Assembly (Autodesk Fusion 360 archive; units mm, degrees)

design "Assembly" references "TOP", "MIRROR-1", "innestiTop", "3DP-mirrors-holder-x1", "baseUV_Front", "3DP-mirrors-holder-x2", "MIRROR-2", "baseUV_Rear", "3DP-mirrors-laser-body", "baseUV_Lateral"
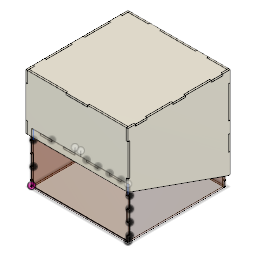
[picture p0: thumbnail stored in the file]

design "TOP" references "Tleft", "Tright", "ps", "Trear", "Tfront", "Ttop"
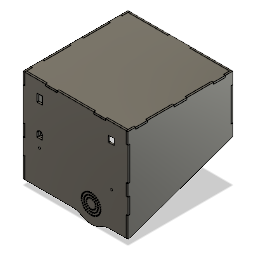
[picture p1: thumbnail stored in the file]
component_insert "Component Insert1"
component_insert "Component Insert2"
component_insert "Component Insert3"
component_insert "Component Insert4"
component_insert "Component Insert5"
component_insert "Component Insert6"
joint "Assemble1" OffsetX 0 OffsetY 0 OffsetZ 0 AngleZ 0 OffsetX 0 OffsetY 0 OffsetZ 0 AngleZ 0 alignAngle 0 alignOffsetX 0 alignOffsetY 0 alignOffsetZ 0
joint "Assemble2" OffsetX 0 OffsetY 0 OffsetZ 0 AngleZ 0 OffsetX 0 OffsetY 0 OffsetZ 0 AngleZ 0 alignAngle 0 alignOffsetX 0 alignOffsetY 0 alignOffsetZ 0
joint "Assemble3" OffsetX 0 OffsetY 0 OffsetZ 0 AngleZ 0 OffsetX 0 OffsetY 0 OffsetZ 0 AngleZ 0 alignAngle -90 alignOffsetX 0 alignOffsetY 0 alignOffsetZ 0
joint "Assemble4" OffsetX 0 OffsetY 0 OffsetZ 0 AngleZ 0 OffsetX 0 OffsetY 0 OffsetZ 0 AngleZ 0 alignAngle -90 alignOffsetX 0 alignOffsetY 0 alignOffsetZ 0
position "Position1"
joint "Assemble5" OffsetX 0 OffsetY 0 OffsetZ 0 AngleZ 0 OffsetX 0 OffsetY 0 OffsetZ 0 AngleZ 0 alignAngle 180 alignOffsetX 0 alignOffsetY 0 alignOffsetZ 0

design "innestiTop"
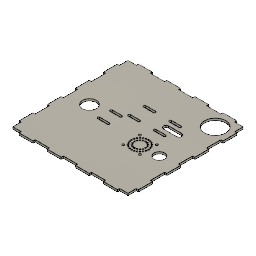
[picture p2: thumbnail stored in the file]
sketch "Sketch1" plane through (0, 0, 0) normal (0, 1, 0) x axis (1, 0, 0)
  line L1 (12, -3) -> (32, -3)
  line L2 (0, 52) -> (0, 32)
  line L3 (92, 0) -> (92, -3)
  line L4 (164, 112) -> (164, 132)
  line L5 (152, 0) -> (164, 0)
  line L6 (92, -3) -> (112, -3)
  line L7 (112, 0) -> (132, 0)
  line L8 (0, 132) -> (0, 112)
  line L9 (0, 0) -> (12, 0)
  line L10 (12, 0) -> (12, -3)
  line L11 (132, 164) -> (112, 164)
  line L12 (167, 112) -> (164, 112)
  line L13 (167, 92) -> (167, 112)
  line L14 (-3, 32) -> (-3, 12)
  line L15 (12, 167) -> (12, 164)
  line L16 (32, 0) -> (52, 0)
  line L17 (-3, 72) -> (-3, 52)
  line L18 (132, -3) -> (152, -3)
  line L19 (52, -3) -> (72, -3)
  line L20 (112, -3) -> (112, 0)
  line L21 (0, 72) -> (-3, 72)
  line L22 (52, 0) -> (52, -3)
  line L23 (0, 92) -> (0, 72)
  line L24 (72, 0) -> (82, 0)
  line L25 (0, 32) -> (-3, 32)
  line L26 (0, 12) -> (0, 0)
  line L27 (-3, 92) -> (0, 92)
  line L28 (82, 0) -> (92, 0)
  line L29 (164, 92) -> (167, 92)
  line L30 (167, 132) -> (167, 152)
  line L31 (32, -3) -> (32, 0)
  line L32 (152, 164) -> (152, 167)
  line L33 (112, 167) -> (92, 167)
  line L34 (132, 167) -> (132, 164)
  line L35 (152, -3) -> (152, 0)
  line L36 (-3, 112) -> (-3, 92)
  line L37 (0, 152) -> (-3, 152)
  line L38 (-3, 52) -> (0, 52)
  line L39 (132, 0) -> (132, -3)
  line L40 (72, 167) -> (52, 167)
  line L41 (164, 132) -> (167, 132)
  line L42 (164, 0) -> (164, 12)
  line L43 (92, 164) -> (82, 164)
  line L44 (72, 164) -> (72, 167)
  line L45 (32, 164) -> (32, 167)
  line L46 (72, -3) -> (72, 0)
  line L47 (-3, 12) -> (0, 12)
  line L48 (167, 52) -> (167, 72)
  line L49 (-3, 132) -> (0, 132)
  line L50 (164, 72) -> (164, 92)
  line L51 (50.0833, 88.2393) -> (64.0834, 88.2393)
  line L52 (164, 152) -> (164, 164)
  line L53 (52, 164) -> (32, 164)
  line L54 (0, 112) -> (-3, 112)
  line L55 (50.0833, 70.4393) -> (64.0834, 70.4393)
  line L56 (-3, 152) -> (-3, 132)
  line L57 (164, 164) -> (152, 164)
  line L58 (92, 167) -> (92, 164)
  line L59 (164, 32) -> (164, 52)
  line L60 (112, 164) -> (112, 167)
  line L61 (119.122, 120.6372) -> (105.122, 120.6372)
  line L62 (152, 167) -> (132, 167)
  line L63 (109.722, 104.7454) -> (128.522, 104.7454)
  line L64 (164, 52) -> (167, 52)
  line L65 (167, 152) -> (164, 152)
  line L66 (0, 164) -> (0, 152)
  line L67 (82, 164) -> (72, 164)
  line L68 (68.5922, 117.4372) -> (82.5922, 117.4372)
  line L69 (82.5922, 98.6372) -> (68.5922, 98.6372)
  line L70 (164, 12) -> (167, 12)
  line L71 (12, 164) -> (0, 164)
  line L72 (167, 12) -> (167, 32)
  line L73 (64.0834, 73.6393) -> (50.0833, 73.6393)
  line L74 (64.0834, 91.4393) -> (50.0833, 91.4393)
  line L75 (68.5922, 95.4372) -> (82.5922, 95.4372)
  line L76 (52, 167) -> (52, 164)
  line L77 (32, 167) -> (12, 167)
  line L78 (105.122, 95.4372) -> (119.122, 95.4372)
  line L79 (82.5922, 120.6372) -> (68.5922, 120.6372)
  line L80 (167, 72) -> (164, 72)
  line L81 (105.122, 117.4372) -> (119.122, 117.4372)
  line L82 (167, 32) -> (164, 32)
  line L83 (128.522, 111.9454) -> (109.722, 111.9454)
  line L84 (119.122, 98.6372) -> (105.122, 98.6372)
  arc A1 centre (119.122, 97.0372) radius 1.6 clockwise from (119.122, 98.6372) to (119.122, 95.4372)
  circle C1 centre (102.282, 62.3858) radius 1
  circle C2 centre (123.0667, 74.3858) radius 1
  circle C3 centre (106.6743, 57.9935) radius 1
  circle C4 centre (104.1891, 59.9005) radius 1
  arc A2 centre (119.122, 119.0372) radius 1.6 clockwise from (119.122, 120.6372) to (119.122, 117.4372)
  arc A3 centre (105.122, 97.0372) radius 1.6 clockwise from (105.122, 95.4372) to (105.122, 98.6372)
  arc A4 centre (82.5922, 97.0372) radius 1.6 clockwise from (82.5922, 98.6372) to (82.5922, 95.4372)
  arc A5 centre (68.5922, 119.0372) radius 1.6 clockwise from (68.5922, 117.4372) to (68.5922, 120.6372)
  circle C5 centre (121.1596, 59.9005) radius 1
  circle C6 centre (100.6743, 68.3858) radius 1
  circle C7 centre (115.7802, 56.7947) radius 1
  circle C8 centre (124.2655, 65.2799) radius 1
  circle C9 centre (118.3312, 74.0426) radius 1
  circle C10 centre (143.9805, 144.0319) radius 15
  circle C11 centre (115.7802, 79.9769) radius 1
  arc A6 centre (109.722, 108.3454) radius 3.6 clockwise from (109.722, 104.7454) to (107.1764, 110.891)
  circle C12 centre (112.6743, 56.3858) radius 1
  circle C13 centre (102.282, 74.3858) radius 1
  circle C14 centre (124.2655, 71.4916) radius 1
  arc A7 centre (82.5922, 119.0372) radius 1.6 clockwise from (82.5922, 120.6372) to (82.5922, 117.4372)
  arc A8 centre (50.0833, 72.0393) radius 1.6 clockwise from (50.0833, 70.4393) to (50.0833, 73.6393)
  arc A9 centre (64.0833, 72.0393) radius 1.6 clockwise from (64.0834, 73.6393) to (64.0834, 70.4393)
  arc A10 centre (105.122, 119.0372) radius 1.6 clockwise from (105.122, 117.4372) to (105.122, 120.6372)
  arc A11 centre (109.593, 108.6567) radius 3.2912 clockwise from (107.1764, 110.891) to (109.722, 111.9454)
  arc A12 centre (128.522, 108.3454) radius 3.6 clockwise from (128.522, 111.9454) to (128.522, 104.7454)
  circle C15 centre (109.5685, 79.9769) radius 1
  circle C16 centre (101.0832, 65.2799) radius 1
  circle C17 centre (107.0175, 62.7289) radius 1
  circle C18 centre (120.6743, 68.3858) radius 1
  circle C19 centre (140.2292, 68.3858) radius 7.5
  circle C20 centre (115.7358, 75.7768) radius 1
  circle C21 centre (106.6743, 78.7781) radius 1
  circle C22 centre (101.0832, 71.4916) radius 1
  circle C23 centre (118.6743, 57.9935) radius 1
  arc A13 centre (68.5922, 97.0372) radius 1.6 clockwise from (68.5922, 95.4372) to (68.5922, 98.6372)
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extrude "Extrude1" new body sketch "Sketch1" along normal blind 3

design "baseUV_Rear"
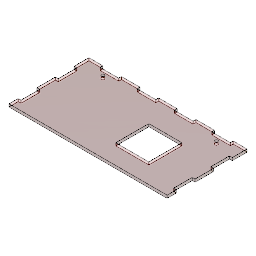
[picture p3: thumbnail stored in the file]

design "baseUV_Front"
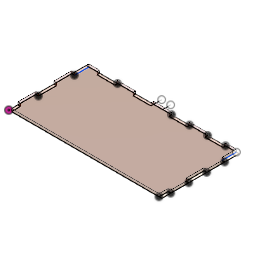
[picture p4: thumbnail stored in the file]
sketch "Sketch1" plane through (0, 0, 0) normal (0, 1, 0) x axis (1, 0, 0)
  line L1 (170, 0) -> (0, 0)
  line L2 (170, 86) -> (170, 0)
  line L3 (0, 86) -> (170, 86)
  line L4 (0, 0) -> (0, 86)
  line L5 (3, 0) -> (0, 0)
  line L6 (3, 10) -> (3, 0)
  line L7 (0, 10) -> (3, 10)
  line L8 (0, 0) -> (0, 10)
  line L9 (0, 30) -> (3, 30)
  line L10 (3, 30) -> (0, 30)
  line L11 (3, 50) -> (3, 30)
  line L12 (0, 50) -> (3, 50)
  line L13 (0, 30) -> (0, 50)
  line L14 (0, 70) -> (3, 70)
  line L15 (3, 70) -> (0, 70)
  line L16 (3, 86) -> (3, 70)
  line L17 (0, 86) -> (3, 86)
  line L18 (0, 70) -> (0, 86)
  line L19 (85, 95) -> (85, 86)
  line L20 (167, 86) -> (167, 70)
  line L21 (167, 70) -> (170, 70)
  line L22 (170, 50) -> (167, 50)
  line L23 (167, 30) -> (170, 30)
  line L24 (170, 10) -> (167, 10)
  line L25 (167, 10) -> (167, 0)
  line L26 (167, 50) -> (167, 30)
  line L27 (75, 95) -> (75, 86)
  line L28 (55, 86) -> (75, 86)
  line L29 (55, 83) -> (55, 86)
  line L30 (75, 83) -> (55, 83)
  line L31 (75, 86) -> (75, 83)
  line L32 (35, 83) -> (35, 86)
  line L33 (15, 83) -> (35, 83)
  line L34 (15, 86) -> (15, 83)
  line L35 (35, 86) -> (15, 86)
  line L36 (35, 83) -> (35, 86)
  line L37 (155, 86) -> (155, 83)
  line L38 (155, 83) -> (135, 83)
  line L39 (135, 83) -> (135, 86)
  line L40 (115, 83) -> (115, 86)
  line L41 (95, 83) -> (115, 83)
  line L42 (95, 86) -> (95, 83)
  point P2 (0, 0)
  point P3 (170, 0)
  point P5 (0, 86)
  point P6 (0, 0)
  point P9 (0, 10)
  point P7 (3, 0)
  point P11 (0, 30)
  point P14 (0, 50)
  point P12 (3, 30)
  point P32 (75, 86)
  point P34 (55, 86)
  point P36 (75, 83)
  point P38 (35, 83)
  point P39 (15, 83)
  point P41 (35, 86)
  dimension "d1" distance P2 P3 = 170
  dimension "d2" distance P2 P5 = 86
  dimension "d3" distance P6 P9 = 10
  dimension "d4" distance P6 P7 = 3
  dimension "d5" = 20
  dimension "d6" distance P11 P14 = 20
  dimension "d7" distance P11 P12 = 3
  dimension "d8" = 20
  dimension "d11" = 10
  dimension "d12" distance P32 P34 = 20
  dimension "d13" distance P32 P36 = 3
  dimension "d14" = 20
  dimension "d15" distance P38 P39 = 20
  dimension "d16" distance P38 P41 = 3
extrude "Extrude2" new body sketch "Sketch1" profile of L1 L2 L3 L4 L6 L7 L9 L10 L11 L12 L14 L15 L16 L20 L21 L22 L23 L24 L25 L26 L29 L30 L31 L32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 along normal blind 3
component_from_bodies "Body->Comp"
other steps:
base_feature "Base Feature"
create_component "CreateComponent1"
remove_body "RemoveBody1"

design "3DP-mirrors-holder-x1"
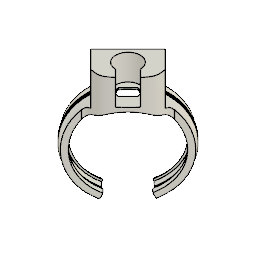
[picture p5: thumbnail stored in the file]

design "Trear"
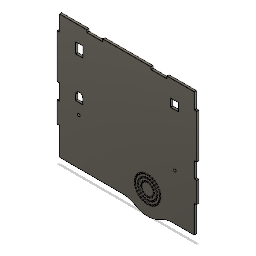
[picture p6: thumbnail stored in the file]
sketch "topRear" plane through (0, 0, 0) normal (0, 0, 1) x axis (1, 0, 0)
  line L1 (-742.1707, 154.2015) -> (-715.123, 154.2015)
  line L2 (-830.923, 309.2015) -> (-850.923, 309.2015)
  line L3 (-888.923, 292.2015) -> (-888.923, 236.2015)
  line L4 (-888.923, 189.2015) -> (-885.923, 189.2015)
  line L5 (-856.173, 278.6015) -> (-856.173, 291.6015)
  line L6 (-744.523, 280.1515) -> (-734.623, 280.1515)
  line L7 (-865.123, 227.2015) -> (-856.223, 227.2015)
  line L8 (-711.323, 292.2015) -> (-714.323, 292.2015)
  line L9 (-885.923, 189.2015) -> (-885.923, 174.2015)
  line L10 (-769.323, 309.2015) -> (-769.323, 312.2015)
  line L11 (-830.923, 312.2015) -> (-830.923, 309.2015)
  line L12 (-711.323, 236.2015) -> (-711.323, 292.2015)
  line L13 (-888.923, 236.2015) -> (-885.923, 236.2015)
  line L14 (-850.923, 312.2015) -> (-885.923, 312.2015)
  line L15 (-714.323, 292.2015) -> (-714.323, 312.2015)
  line L16 (-885.923, 312.2015) -> (-885.923, 292.2015)
  line L17 (-714.323, 154.2015) -> (-714.323, 174.2015)
  line L18 (-744.523, 290.0515) -> (-744.523, 280.1515)
  line L19 (-769.323, 312.2015) -> (-830.923, 312.2015)
  line L20 (-856.223, 227.2015) -> (-856.223, 234.1515)
  line L21 (-885.923, 236.2015) -> (-885.923, 216.2015)
  line L22 (-856.173, 291.6015) -> (-865.173, 291.6015)
  line L23 (-714.323, 174.2015) -> (-714.323, 189.2015)
  line L24 (-865.173, 278.6015) -> (-856.173, 278.6015)
  line L25 (-715.123, 154.2015) -> (-714.323, 154.2015)
  line L26 (-885.923, 292.2015) -> (-888.923, 292.2015)
  line L27 (-734.623, 280.1515) -> (-734.623, 290.0515)
  line L28 (-711.323, 216.2015) -> (-714.323, 216.2015)
  line L29 (-885.923, 154.2015) -> (-805.3845, 154.2015)
  line L30 (-850.923, 309.2015) -> (-850.923, 312.2015)
  line L31 (-714.323, 216.2015) -> (-714.323, 236.2015)
  line L32 (-865.173, 291.6015) -> (-865.173, 278.6015)
  line L33 (-749.323, 312.2015) -> (-749.323, 309.2015)
  line L34 (-749.323, 309.2015) -> (-769.323, 309.2015)
  line L35 (-714.323, 189.2015) -> (-711.323, 189.2015)
  line L36 (-714.323, 236.2015) -> (-711.323, 236.2015)
  line L37 (-885.923, 174.2015) -> (-885.923, 154.2015)
  line L38 (-865.123, 234.1515) -> (-865.123, 227.2015)
  line L39 (-714.323, 312.2015) -> (-749.323, 312.2015)
  line L40 (-885.923, 216.2015) -> (-888.923, 216.2015)
  line L41 (-888.923, 216.2015) -> (-888.923, 189.2015)
  line L42 (-711.323, 189.2015) -> (-711.323, 216.2015)
  line L43 (-734.623, 290.0515) -> (-744.523, 290.0515)
  circle C1 centre (-779.4345, 169.5446) radius 1
  circle C2 centre (-773.7776, 167.2015) radius 1
  circle C3 centre (-776.8391, 182.5925) radius 1
  circle C4 centre (-766.3866, 172.14) radius 1
  arc A1 centre (-742.1707, 124.2015) radius 30 clockwise from (-757.9742, 149.7015) to (-742.1707, 154.2015)
  circle C5 centre (-779.4345, 180.8583) radius 1
  circle C6 centre (-781.1687, 178.263) radius 1
  circle C7 centre (-773.7776, 187.2015) radius 1
  arc A2 centre (-860.673, 234.1515) radius 4.45 clockwise from (-865.123, 234.1515) to (-856.223, 234.1515)
  circle C8 centre (-781.7776, 175.2015) radius 1
  circle C9 centre (-781.1687, 172.14) radius 1
  circle C10 centre (-776.8391, 167.8105) radius 1
  circle C11 centre (-770.7161, 167.8105) radius 1
  circle C12 centre (-768.1208, 169.5446) radius 1
  circle C13 centre (-773.7776, 191.2015) radius 1
  circle C14 centre (-765.7776, 175.2015) radius 1
  circle C15 centre (-773.7776, 183.2015) radius 1
  circle C16 centre (-785.3687, 178.3073) radius 1
  circle C17 centre (-782.2629, 166.7162) radius 1
  circle C18 centre (-785.3687, 172.0957) radius 1
  circle C19 centre (-767.7776, 164.8092) radius 1
  arc A3 centre (-805.3845, 124.2015) radius 30 clockwise from (-805.3845, 154.2015) to (-789.5811, 149.7015)
  arc A4 centre (-773.7776, 175.2015) radius 30 clockwise from (-757.9742, 149.7015) to (-789.5811, 149.7015)
  circle C20 centre (-760.4741, 166.3124) radius 1
  circle C21 centre (-758.0851, 172.08) radius 1
  circle C22 centre (-782.6667, 188.505) radius 1
  circle C23 centre (-782.2629, 183.6868) radius 1
  circle C24 centre (-779.9006, 160.4194) radius 1
  circle C25 centre (-770.6562, 159.5089) radius 1
  circle C26 centre (-788.5597, 169.0786) radius 1
  circle C27 centre (-758.9955, 181.3244) radius 1
  circle C28 centre (-766.3866, 178.263) radius 1
  circle C29 centre (-770.7161, 182.5925) radius 1
  circle C30 centre (-787.0811, 184.0906) radius 1
  circle C31 centre (-762.4639, 186.5152) radius 1
  circle C32 centre (-757.7776, 175.2015) radius 1
  circle C33 centre (-776.8834, 163.6104) radius 1
  circle C34 centre (-785.0913, 163.8878) radius 1
  circle C35 centre (-779.7776, 164.8092) radius 1
  circle C36 centre (-785.7776, 175.2015) radius 1
  circle C37 centre (-776.8991, 190.8941) radius 1
  circle C38 centre (-758.0851, 178.3229) radius 1
  circle C39 centre (-785.0913, 186.5152) radius 1
  circle C40 centre (-762.1865, 178.3073) radius 1
  circle C41 centre (-788.5597, 181.3244) radius 1
  circle C42 centre (-767.6547, 189.9836) radius 1
  circle C43 centre (-763.3853, 181.2015) radius 1
  circle C44 centre (-758.9955, 169.0786) radius 1
  circle C45 centre (-760.4741, 184.0906) radius 1
  circle C46 centre (-768.1208, 180.8583) radius 1
  circle C47 centre (-773.7776, 163.2015) radius 1
  circle C48 centre (-767.7776, 185.5938) radius 1
  circle C49 centre (-784.1699, 181.2015) radius 1
  circle C50 centre (-762.4639, 163.8878) radius 1
  circle C51 centre (-770.6718, 186.7926) radius 1
  circle C52 centre (-765.2923, 183.6868) radius 1
  circle C53 centre (-763.3853, 169.2015) radius 1
  circle C54 centre (-787.0811, 166.3124) radius 1
  circle C55 centre (-767.6547, 160.4194) radius 1
  circle C56 centre (-789.7776, 175.2015) radius 1
  circle C57 centre (-776.8834, 186.7926) radius 1
  circle C58 centre (-761.7776, 175.2015) radius 1
  circle C59 centre (-770.6562, 190.8941) radius 1
  circle C60 centre (-764.8885, 188.505) radius 1
  circle C61 centre (-764.8885, 161.898) radius 1
  circle C62 centre (-773.7776, 159.2015) radius 1
  circle C63 centre (-789.4702, 172.08) radius 1
  circle C64 centre (-779.9006, 189.9836) radius 1
  circle C65 centre (-789.4702, 178.3229) radius 1
  circle C66 centre (-776.8991, 159.5089) radius 1
  circle C67 centre (-739.123, 213.2014) radius 1.6
  circle C68 centre (-784.1699, 169.2015) radius 1
  circle C69 centre (-861.123, 213.2014) radius 1.6
  circle C70 centre (-779.7776, 185.5938) radius 1
  circle C71 centre (-770.6718, 163.6104) radius 1
  circle C72 centre (-765.2923, 166.7162) radius 1
  circle C73 centre (-782.6667, 161.898) radius 1
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extrude "Extrude1" new body sketch "topRear" along normal blind 3

design "3DP-mirrors-holder-x2"
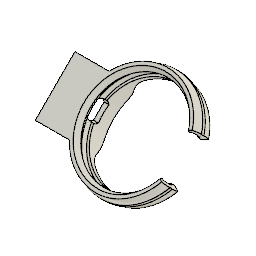
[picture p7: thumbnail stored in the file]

design "MIRROR-2"
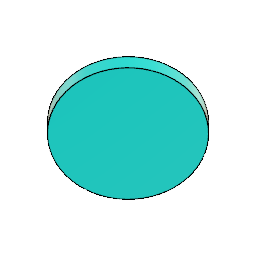
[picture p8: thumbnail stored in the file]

design "ps"
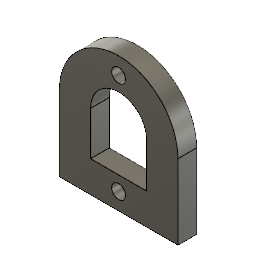
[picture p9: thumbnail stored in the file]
sketch "topPowerSupply" plane through (0, 0, 0) normal (0, 0, 1) x axis (1, 0, 0)
  line L1 (-593.1333, 438.9132) -> (-593.1333, 450.8632)
  line L2 (-607.0333, 450.8632) -> (-607.0333, 443.9132)
  line L3 (-612.0333, 438.9132) -> (-593.1333, 438.9132)
  line L4 (-598.1333, 443.9132) -> (-598.1333, 450.8632)
  line L5 (-607.0333, 443.9132) -> (-598.1333, 443.9132)
  line L6 (-612.0333, 450.8632) -> (-612.0333, 438.9132)
  circle C1 centre (-602.5833, 441.6132) radius 1.1
  arc A1 centre (-602.5833, 450.8632) radius 9.45 clockwise from (-612.0333, 450.8632) to (-593.1333, 450.8632)
  circle C2 centre (-602.5833, 457.6132) radius 1.1
  arc A2 centre (-602.5833, 450.8632) radius 4.45 clockwise from (-607.0333, 450.8632) to (-598.1333, 450.8632)
extrude "Extrude1" new body sketch "topPowerSupply" along normal blind 3

design "baseUV_Lateral"
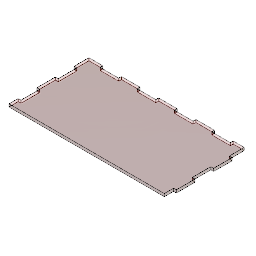
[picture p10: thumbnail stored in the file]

design "Tright"
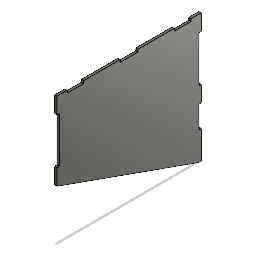
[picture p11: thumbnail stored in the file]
sketch "topRight" plane through (0, 0, 0) normal (1, 0, 0) x axis (0, 0, -1)
  line L1 (-505.2969, 687.289) -> (-505.2969, 707.289)
  line L2 (-472.2969, 707.289) -> (-427.2969, 707.289)
  line L3 (-502.2969, 687.289) -> (-505.2969, 687.289)
  line L4 (-330.6969, 631.289) -> (-327.6969, 631.289)
  line L5 (-492.2969, 704.289) -> (-472.2969, 704.289)
  line L6 (-505.2969, 707.289) -> (-502.2969, 707.289)
  line L7 (-427.2969, 704.289) -> (-405.6969, 704.289)
  line L8 (-405.6969, 707.289) -> (-360.6969, 707.289)
  line L9 (-427.2969, 707.289) -> (-427.2969, 704.289)
  line L10 (-502.2969, 707.289) -> (-492.2969, 707.289)
  line L11 (-340.6969, 707.289) -> (-330.6969, 707.289)
  line L12 (-330.6969, 611.289) -> (-330.6969, 584.289)
  line L13 (-327.6969, 569.289) -> (-327.6969, 549.289)
  line L14 (-360.6969, 704.289) -> (-340.6969, 704.289)
  line L15 (-330.6969, 707.289) -> (-327.6969, 707.289)
  line L16 (-327.6969, 611.289) -> (-330.6969, 611.289)
  line L17 (-330.6969, 584.289) -> (-327.6969, 584.289)
  line L18 (-505.2969, 611.289) -> (-505.2969, 631.289)
  line L19 (-505.2969, 631.289) -> (-502.2969, 631.289)
  line L20 (-327.6969, 707.289) -> (-327.6969, 687.289)
  line L21 (-472.2969, 704.289) -> (-472.2969, 707.289)
  line L22 (-502.2969, 631.289) -> (-502.2969, 687.289)
  line L23 (-327.6969, 549.289) -> (-330.6969, 549.289)
  line L24 (-327.6969, 687.289) -> (-330.6969, 687.289)
  line L25 (-360.6969, 707.289) -> (-360.6969, 704.289)
  line L26 (-405.6969, 704.289) -> (-405.6969, 707.289)
  line L27 (-492.2969, 707.289) -> (-492.2969, 704.289)
  line L28 (-327.6969, 631.289) -> (-327.6969, 611.289)
  line L29 (-330.6969, 687.289) -> (-330.6969, 631.289)
  line L30 (-340.6969, 704.289) -> (-340.6969, 707.289)
  line L31 (-327.6969, 584.289) -> (-327.6969, 569.289)
  line L32 (-330.6969, 549.289) -> (-505.2969, 611.289)
extrude "Extrude1" new body sketch "topRight" along normal blind 3

design "Tleft"
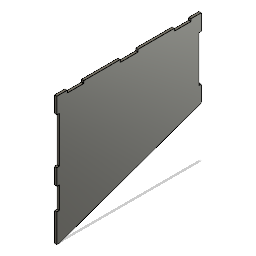
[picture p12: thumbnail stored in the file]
sketch "topLeft" plane through (0, 0, 0) normal (1, 0, 0) x axis (0, 0, -1)
  line L1 (-549.8627, 631.289) -> (-552.8627, 631.289)
  line L2 (-727.4627, 631.289) -> (-727.4627, 611.289)
  line L3 (-562.8627, 707.289) -> (-562.8627, 704.289)
  line L4 (-549.8627, 687.289) -> (-549.8627, 707.289)
  line L5 (-727.4627, 687.289) -> (-724.4627, 687.289)
  line L6 (-582.8627, 704.289) -> (-582.8627, 707.289)
  line L7 (-549.8627, 707.289) -> (-552.8627, 707.289)
  line L8 (-627.8627, 707.289) -> (-627.8627, 704.289)
  line L9 (-724.4627, 611.289) -> (-724.4627, 584.289)
  line L10 (-627.8627, 704.289) -> (-649.4627, 704.289)
  line L11 (-549.8627, 611.289) -> (-549.8627, 631.289)
  line L12 (-727.4627, 707.289) -> (-727.4627, 687.289)
  line L13 (-714.4627, 707.289) -> (-724.4627, 707.289)
  line L14 (-724.4627, 707.289) -> (-727.4627, 707.289)
  line L15 (-714.4627, 704.289) -> (-714.4627, 707.289)
  line L16 (-724.4627, 631.289) -> (-727.4627, 631.289)
  line L17 (-694.4627, 707.289) -> (-694.4627, 704.289)
  line L18 (-552.8627, 631.289) -> (-552.8627, 687.289)
  line L19 (-727.4627, 549.289) -> (-724.4627, 549.289)
  line L20 (-552.8627, 687.289) -> (-549.8627, 687.289)
  line L21 (-649.4627, 704.289) -> (-649.4627, 707.289)
  line L22 (-727.4627, 584.289) -> (-727.4627, 569.289)
  line L23 (-727.4627, 611.289) -> (-724.4627, 611.289)
  line L24 (-582.8627, 707.289) -> (-627.8627, 707.289)
  line L25 (-649.4627, 707.289) -> (-694.4627, 707.289)
  line L26 (-724.4627, 687.289) -> (-724.4627, 631.289)
  line L27 (-724.4627, 549.289) -> (-549.8627, 611.289)
  line L28 (-552.8627, 707.289) -> (-562.8627, 707.289)
  line L29 (-724.4627, 584.289) -> (-727.4627, 584.289)
  line L30 (-562.8627, 704.289) -> (-582.8627, 704.289)
  line L31 (-727.4627, 569.289) -> (-727.4627, 549.289)
  line L32 (-694.4627, 704.289) -> (-714.4627, 704.289)
extrude "Extrude1" new body sketch "topLeft" along normal blind 3

design "Ttop"
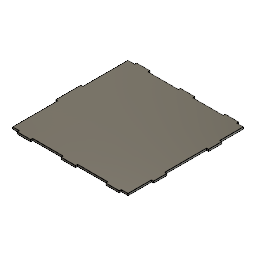
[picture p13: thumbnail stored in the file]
sketch "topTop" plane through (0, 0, 0) normal (0, 1, 0) x axis (1, 0, 0)
  line L1 (-773.8423, 568.7857) -> (-773.8423, 533.7858)
  line L2 (-870.4423, 571.7857) -> (-848.8423, 571.7857)
  line L3 (-803.8423, 568.7857) -> (-803.8423, 571.7857)
  line L4 (-783.8423, 397.1858) -> (-783.8423, 394.1858)
  line L5 (-770.8423, 452.1858) -> (-770.8423, 432.1858)
  line L6 (-773.8423, 533.7858) -> (-770.8423, 533.7858)
  line L7 (-770.8423, 513.7858) -> (-773.8423, 513.7858)
  line L8 (-848.8423, 568.7857) -> (-803.8423, 568.7857)
  line L9 (-770.8423, 533.7858) -> (-770.8423, 513.7858)
  line L10 (-870.4423, 568.7857) -> (-870.4423, 571.7857)
  line L11 (-935.4423, 568.7857) -> (-935.4423, 571.7857)
  line L12 (-773.8423, 397.1858) -> (-783.8423, 397.1858)
  line L13 (-935.4423, 571.7857) -> (-915.4423, 571.7857)
  line L14 (-915.4423, 568.7857) -> (-870.4423, 568.7857)
  line L15 (-848.8423, 397.1858) -> (-848.8423, 394.1858)
  line L16 (-803.8423, 397.1858) -> (-848.8423, 397.1858)
  line L17 (-770.8423, 432.1858) -> (-773.8423, 432.1858)
  line L18 (-773.8423, 483.7858) -> (-773.8423, 452.1858)
  line L19 (-773.8423, 432.1858) -> (-773.8423, 397.1858)
  line L20 (-848.8423, 571.7857) -> (-848.8423, 568.7857)
  line L21 (-773.8423, 513.7858) -> (-773.8423, 483.7858)
  line L22 (-803.8423, 394.1858) -> (-803.8423, 397.1858)
  line L23 (-803.8423, 571.7857) -> (-783.8423, 571.7857)
  line L24 (-783.8423, 394.1858) -> (-803.8423, 394.1858)
  line L25 (-783.8423, 568.7857) -> (-773.8423, 568.7857)
  line L26 (-783.8423, 571.7857) -> (-783.8423, 568.7857)
  line L27 (-915.4423, 571.7857) -> (-915.4423, 568.7857)
  line L28 (-948.4423, 464.1858) -> (-948.4423, 501.7858)
  line L29 (-935.4423, 397.1858) -> (-945.4423, 397.1858)
  line L30 (-945.4423, 464.1858) -> (-948.4423, 464.1858)
  line L31 (-945.4423, 568.7857) -> (-935.4423, 568.7857)
  line L32 (-948.4423, 501.7858) -> (-945.4423, 501.7858)
  line L33 (-870.4423, 394.1858) -> (-870.4423, 397.1858)
  line L34 (-945.4423, 397.1858) -> (-945.4423, 464.1858)
  line L35 (-915.4423, 394.1858) -> (-935.4423, 394.1858)
  line L36 (-850.4423, 394.1858) -> (-870.4423, 394.1858)
  line L37 (-848.8423, 394.1858) -> (-850.4423, 394.1858)
  line L38 (-945.4423, 501.7858) -> (-945.4423, 568.7857)
  line L39 (-915.4423, 397.1858) -> (-915.4423, 394.1858)
  line L40 (-935.4423, 394.1858) -> (-935.4423, 397.1858)
  line L41 (-773.8423, 452.1858) -> (-770.8423, 452.1858)
  line L42 (-870.4423, 397.1858) -> (-915.4423, 397.1858)
extrude "Extrude1" new body sketch "topTop" along normal blind 3

design "MIRROR-1"
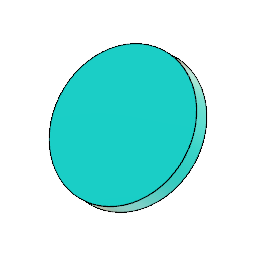
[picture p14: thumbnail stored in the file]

design "3DP-mirrors-laser-body"
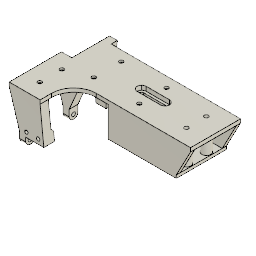
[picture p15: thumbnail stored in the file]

design "Tfront"
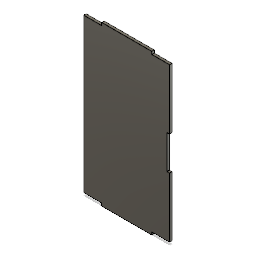
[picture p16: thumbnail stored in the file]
sketch "topFront" plane through (0, 0, 0) normal (0, 0, 1) x axis (1, 0, 0)
  line L1 (-139.5934, 683.1301) -> (-139.5934, 684.7301)
  line L2 (-156.5934, 751.7301) -> (-156.5934, 754.7301)
  line L3 (-136.5934, 647.1301) -> (-139.5934, 647.1301)
  line L4 (-212.5934, 751.7301) -> (-232.5934, 751.7301)
  line L5 (-212.5934, 577.1302) -> (-156.5934, 577.1302)
  line L6 (-136.5934, 684.7301) -> (-136.5934, 751.7301)
  line L7 (-156.5934, 577.1302) -> (-156.5934, 580.1302)
  line L8 (-136.5934, 751.7301) -> (-156.5934, 751.7301)
  line L9 (-136.5934, 580.1302) -> (-136.5934, 647.1301)
  line L10 (-139.5934, 647.1301) -> (-139.5934, 683.1301)
  line L11 (-139.5934, 684.7301) -> (-136.5934, 684.7301)
  line L12 (-156.5934, 754.7301) -> (-212.5934, 754.7301)
  line L13 (-212.5934, 754.7301) -> (-212.5934, 751.7301)
  line L14 (-212.5934, 580.1302) -> (-212.5934, 577.1302)
  line L15 (-156.5934, 580.1302) -> (-136.5934, 580.1302)
  line L16 (-232.5934, 751.7301) -> (-232.5934, 580.1302)
  line L17 (-232.5934, 580.1302) -> (-212.5934, 580.1302)
extrude "Extrude1" new body sketch "topFront" along normal blind 3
